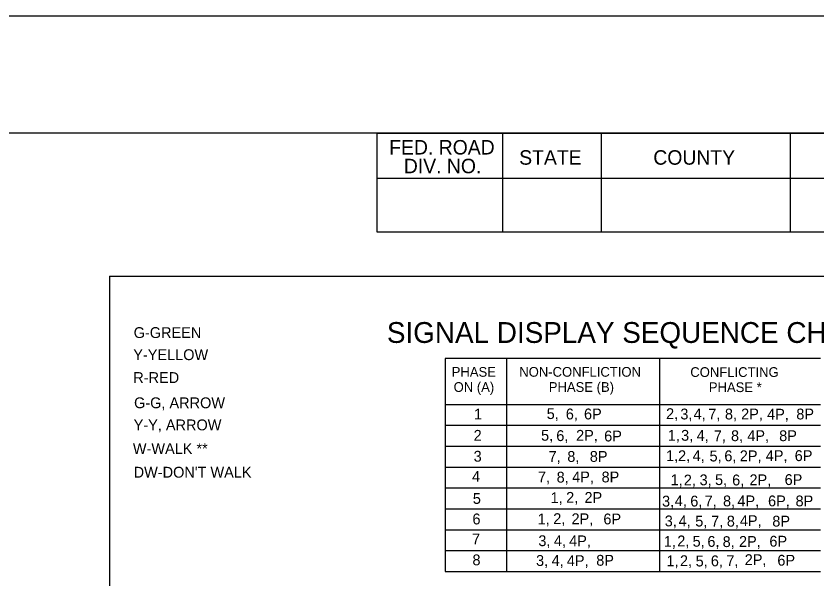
# Model space of a CAD drawing. Extents: x 0 to 3.01, y -0.05 to 1.83.
# Drawn here: x 2.2522 to 2.6475, y 1.5553 to 1.8333 of the extents above; entities that cross this region are included whole.
import ezdxf

# ---------------------------------------------------------------- set-up
doc = ezdxf.new("R2010")
doc.units = 0
for name, color, linetype in [('RD_SHT_IplotShp', 7, 'Continuous'), ('TR_TS_Border', 7, 'Continuous'), ('TR_TS_Phase1', 7, 'Continuous'), ('TR_TS_Phase2', 7, 'Continuous'), ('TR_TS_Phase3', 7, 'Continuous'), ('TR_TS_Phase4', 7, 'Continuous'), ('TR_TS_Phase5', 7, 'Continuous'), ('TR_TS_Phase6', 7, 'Continuous'), ('TR_TS_Phase7', 7, 'Continuous'), ('TR_TS_Phase8', 7, 'Continuous')]:
    doc.layers.add(name, color=color, linetype=linetype)

msp = doc.modelspace()

# ---------------------------------------------------------------- linework, layer by layer
at = {"layer": 'RD_SHT_IplotShp'}
msp.add_lwpolyline([(0, 0), (3, 0), (3, 1.83333), (0, 1.83333)], close=True, dxfattribs=at)
at = {"layer": 'TR_TS_Border'}
for p, q in [((2.97124, 1.83333), (0.031, 1.83333)), ((2.96235, 1.7754), (0.16861, 1.7754)), ((2.49245, 1.72662), (2.49245, 1.7754)), ((2.54123, 1.72662), (2.54123, 1.7754)), ((2.63434, 1.72662), (2.63434, 1.7754)), ((2.43041, 1.75323), (2.96235, 1.75323)), ((2.29837, 1.70495), (2.29837, 1.27559)), ((2.29837, 1.70495), (2.90748, 1.70495)), ((2.46395, 1.66424), (2.46395, 1.55906)), ((2.6492, 1.66424), (2.46395, 1.66424)), ((2.4942, 1.66424), (2.4942, 1.55906)), ((2.56979, 1.66424), (2.56979, 1.55906)), ((2.46395, 1.64152), (2.6492, 1.64152)), ((2.46395, 1.63122), (2.6492, 1.63122)), ((2.46395, 1.62091), (2.6492, 1.62091)), ((2.46395, 1.6106), (2.6492, 1.6106)), ((2.46395, 1.60029), (2.6492, 1.60029)), ((2.46395, 1.58999), (2.6492, 1.58999)), ((2.46395, 1.57968), (2.6492, 1.57968)), ((2.46395, 1.56937), (2.6492, 1.56937)), ((2.46395, 1.55906), (2.6492, 1.55906))]:
    msp.add_line(p, q, dxfattribs=at)
msp.add_lwpolyline([(2.96235, 1.7754), (2.96235, 1.72662), (2.43041, 1.72662), (2.43041, 1.7754)], close=True, dxfattribs=at)

# ---------------------------------------------------------------- texts
for s, height, p in [('FED. ROAD', 0.007148, (2.43639, 1.76494)), ('STATE', 0.007148, (2.50053, 1.75991)), ('COUNTY', 0.007148, (2.56672, 1.75991)), ('DIV. NO.', 0.007148, (2.44361, 1.75569)), ('SIGNAL DISPLAY SEQUENCE CHART', 0.0102811, (2.43525, 1.67191)), ('G-GREEN', 0.005347, (2.31029, 1.67433)), ('Y-YELLOW', 0.005347, (2.3101, 1.66342)), ('PHASE', 0.004812, (2.46724, 1.6552)), ('NON-CONFLICTION', 0.0048122, (2.50057, 1.65521)), ('R-RED', 0.005347, (2.3101, 1.65212)), ('CONFLICTING', 0.0048122, (2.58497, 1.65511)), ('ON (A)', 0.004812, (2.46818, 1.64772)), ('PHASE (B)', 0.004812, (2.51514, 1.64773)), ('PHASE *', 0.004812, (2.59412, 1.64763)), ('G-G, ARROW', 0.005347, (2.31048, 1.63966)), ('Y-Y, ARROW', 0.005347, (2.31029, 1.62875)), ('W-WALK **', 0.005347, (2.3099, 1.61706)), ("DW-DON'T WALK", 0.0053469, (2.31029, 1.60538))]:
    msp.add_text(s, height=height, dxfattribs=at).set_placement(p)
at = {"layer": 'TR_TS_Phase1'}
for s, height, p in [('1', 0.00535, (2.47825, 1.63411)), ('1,', 0.005347, (2.57387, 1.62363)), ('1,', 0.005347, (2.57302, 1.61358)), ('1,', 0.005347, (2.57528, 1.60165)), ('1,', 0.005347, (2.51601, 1.59282)), ('1,', 0.005347, (2.50962, 1.5823)), ('1,', 0.005347, (2.57189, 1.57122)), ('1,', 0.005347, (2.57321, 1.56164))]:
    msp.add_text(s, height=height, dxfattribs=at).set_placement(p)
at = {"layer": 'TR_TS_Phase2'}
for s, height, p in [('2,', 0.005347, (2.57301, 1.6343)), ('2P,', 0.005347, (2.61004, 1.63414)), ('2', 0.00535, (2.47806, 1.62359)), ('2P,', 0.005347, (2.52861, 1.62359)), ('2,', 0.005347, (2.57893, 1.61354)), ('2P,', 0.005347, (2.60938, 1.61348)), ('2,', 0.005347, (2.58175, 1.60152)), ('2P,', 0.005347, (2.61417, 1.60164)), ('2,', 0.005347, (2.5237, 1.59297)), ('2P', 0.005347, (2.53274, 1.59291)), ('2,', 0.005347, (2.51732, 1.58245)), ('2P,', 0.005347, (2.52635, 1.58239)), ('2,', 0.005347, (2.57856, 1.57146)), ('2P,', 0.005347, (2.609, 1.57121)), ('2,', 0.005347, (2.57987, 1.56169)), ('2P,', 0.005347, (2.61182, 1.5622))]:
    msp.add_text(s, height=height, dxfattribs=at).set_placement(p)
at = {"layer": 'TR_TS_Phase3'}
for s, height, p in [('3,', 0.005347, (2.58006, 1.63412)), ('3,', 0.005347, (2.58043, 1.6236)), ('3', 0.00535, (2.47806, 1.61327)), ('3,', 0.005347, (2.58955, 1.60162)), ('3,', 0.005347, (2.57104, 1.5911)), ('3,', 0.005347, (2.57236, 1.58133)), ('3,', 0.005347, (2.50999, 1.57156)), ('3,', 0.005347, (2.50886, 1.56179))]:
    msp.add_text(s, height=height, dxfattribs=at).set_placement(p)
at = {"layer": 'TR_TS_Phase4'}
for s, height, p in [('4,', 0.005347, (2.58661, 1.63414)), ('4P,', 0.005347, (2.62286, 1.63405)), ('4,', 0.005347, (2.58811, 1.62353)), ('4P,', 0.005347, (2.61309, 1.62344)), ('4,', 0.005347, (2.58614, 1.61357)), ('4P,', 0.005347, (2.6222, 1.61358)), ('4', 0.00535, (2.47728, 1.60333)), ('4P,', 0.005347, (2.52668, 1.60306)), ('4,', 0.005347, (2.57731, 1.59131)), ('4P,', 0.005347, (2.60821, 1.59122)), ('4,', 0.005347, (2.57919, 1.58135)), ('4P,', 0.005347, (2.60943, 1.58146)), ('4,', 0.005347, (2.51767, 1.57159)), ('4P,', 0.005347, (2.52518, 1.5715)), ('4,', 0.005347, (2.51654, 1.56182)), ('4P,', 0.005347, (2.52405, 1.56173))]:
    msp.add_text(s, height=height, dxfattribs=at).set_placement(p)
at = {"layer": 'TR_TS_Phase5'}
for s, height, p in [('5,', 0.005347, (2.51411, 1.63432)), ('5,', 0.005347, (2.51133, 1.62361)), ('5,', 0.005347, (2.59446, 1.61337)), ('5,', 0.005347, (2.59718, 1.60172)), ('5', 0.00535, (2.47767, 1.59243)), ('5,', 0.005347, (2.58741, 1.58125)), ('5,', 0.005347, (2.5861, 1.57129)), ('5,', 0.005347, (2.5876, 1.56152))]:
    msp.add_text(s, height=height, dxfattribs=at).set_placement(p)
at = {"layer": 'TR_TS_Phase6'}
for s, height, p in [('6,', 0.005347, (2.52353, 1.63414)), ('6P', 0.005347, (2.53251, 1.63414)), ('6,', 0.005347, (2.51884, 1.62344)), ('6P', 0.005347, (2.54247, 1.62325)), ('6,', 0.005347, (2.60177, 1.61348)), ('6P', 0.005347, (2.63649, 1.61357)), ('6,', 0.005347, (2.60562, 1.60155)), ('6P', 0.005347, (2.63151, 1.60174)), ('6,', 0.005347, (2.58496, 1.59113)), ('6P,', 0.005347, (2.62334, 1.59122)), ('6', 0.00535, (2.47747, 1.5823)), ('6P', 0.005347, (2.54208, 1.5823)), ('6,', 0.005347, (2.59341, 1.57121)), ('6P', 0.005347, (2.624, 1.57131)), ('6,', 0.005347, (2.5951, 1.56163)), ('6P', 0.005347, (2.62794, 1.56192))]:
    msp.add_text(s, height=height, dxfattribs=at).set_placement(p)
at = {"layer": 'TR_TS_Phase7'}
for s, height, p in [('7,', 0.005347, (2.59384, 1.6341)), ('7,', 0.005347, (2.59656, 1.62339)), ('7,', 0.005347, (2.51504, 1.61317)), ('7,', 0.005347, (2.50978, 1.60301)), ('7,', 0.005347, (2.59205, 1.59118)), ('7,', 0.005347, (2.59525, 1.58122)), ('7', 0.00535, (2.47728, 1.5724)), ('7,', 0.005347, (2.60276, 1.56169))]:
    msp.add_text(s, height=height, dxfattribs=at).set_placement(p)
at = {"layer": 'TR_TS_Phase8'}
for s, height, p in [('8,', 0.005347, (2.60205, 1.63412)), ('8P', 0.005347, (2.63728, 1.63412)), ('8,', 0.005347, (2.60506, 1.62341)), ('8P', 0.005347, (2.62882, 1.62341)), ('8,', 0.005347, (2.52428, 1.61318)), ('8P', 0.005347, (2.53537, 1.61318)), ('8,', 0.005347, (2.51902, 1.60297)), ('8P', 0.005347, (2.54119, 1.60303)), ('8,', 0.005347, (2.60112, 1.5912)), ('8P', 0.005347, (2.6369, 1.5912)), ('8,', 0.005347, (2.60299, 1.58124)), ('8P', 0.005347, (2.62544, 1.58124)), ('8,', 0.005347, (2.60093, 1.5711)), ('8', 0.00535, (2.47747, 1.56208)), ('8P', 0.005347, (2.53856, 1.56189))]:
    msp.add_text(s, height=height, dxfattribs=at).set_placement(p)

doc.saveas('drawing.dxf')
